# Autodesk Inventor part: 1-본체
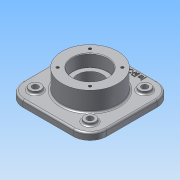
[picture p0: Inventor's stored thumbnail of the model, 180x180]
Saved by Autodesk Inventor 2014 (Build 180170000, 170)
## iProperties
Created: 2015-09
Part Number: 1-본체
Material: 알루미늄 6061
Document SubType Name: Modeling
Designer: study
Density: 2.71 g/cm^3
Appearance: 알루미늄 - 평지
Mass: 1464.68 g
Surface Area: 800.934 cm^2
Volume: 540.471 cm^3
Author: study
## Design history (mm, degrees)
sketch "스케치1"
  geometry: L1 (-75, -75)-(75, -75); L2 (75, -75)-(75, 75); L3 (75, 75)-(-75, 75); L4 (-75, 75)-(-75, -75); L5 (-75, -75)-(75, 75); L6 (75, -75)-(-75, 75); 1 further point
  constraints: 12 end point, 2 midpoint, 2 parallel, 2 perpendicular, 1 horizontal
  dimensions: "d0" = 150 distance of L2.end L3.end
extrude "돌출1" new body sketch "스케치1" distance "d1" = 12; taper "d2" = 0 deg
fillet "모깎기1" dims "d3" = 30
node "작업 평면1"
sketch "스케치2"
  geometry: C1 r 50 at (0, 0); 1 further point
  constraints: 1 centre point, 1 coincident
  dimensions: "d5" = 100 diameter of C1
extrude "돌출2" join sketch "스케치2" distance "d7" = 70; taper "d8" = 0 deg
sketch "스케치3"
  geometry: C1 r 50 at (0, 0) reference; C2 r 10 at (-49, 49); C3 r 10 at (49, 49); C4 r 10 at (-49, -49); C5 r 10 at (49, -49)
  constraints: 4 centre point, 3 equal radius, 2 horizontal alignment, 2 vertical alignment
  dimensions: "d45" = 20 diameter of C2; "d46" = 98 distance of C3.centre C2.centre; "d47" = 49 horizontal distance of C1.centre C2.centre; "d48" = 98 distance of C2.centre C4.centre; "d49" = 49 horizontal distance of C4.centre C1.centre
extrude "돌출3" join sketch "스케치3" distance "d10" = 5; taper "d11" = 0 deg
sketch "스케치7"
  geometry: C1 r 10 at (0, 0) reference; C2 r 10 at (98, 0) reference; C3 r 10 at (0, -98) reference; C4 r 10 at (98, -98) reference; 5 further points
  constraints: 4 coincident
hole "구멍4" sketch "스케치7" at (0, 0), (98, 0), (98, -98), (0, -98) diameter "d51" = 11; stored, may be unused: countersink angle "d55" = 90 deg, drill point angle "d57" = 0 deg; dims "d52" = 10, "d53" = 62, "d54" = 22, "d56" = 13
hole "구멍1" diameter "d18" = 45; stored, may be unused: countersink angle "d22" = 90 deg, drill point angle "d24" = 0 deg; dims "d16" = 10, "d17" = 10, "d19" = 6, "d20" = 62, "d21" = 22, "d23" = 80
hole "구멍2" diameter "d27" = 45; stored, may be unused: countersink angle "d31" = 90 deg, drill point angle "d33" = 0 deg; dims "d25" = 10, "d26" = 10, "d28" = 6, "d29" = 62, "d30" = 22, "d32" = 80
sketch "스케치5" dims "d34" = 82
  geometry: L1 (-28.991, -28.991)-(28.991, -28.991); L2 (28.991, -28.991)-(28.991, 28.991); L3 (28.991, 28.991)-(-28.991, 28.991); L4 (-28.991, 28.991)-(-28.991, -28.991); L5 (-28.991, -28.991)-(28.991, 28.991); L6 (28.991, -28.991)-(-28.991, 28.991); C1 r 50 at (0, 0) reference; 5 further points
  constraints: 12 end point, 5 coincident, 2 midpoint, 2 parallel, 2 perpendicular, 1 horizontal, 3 other
hole "구멍3" sketch "스케치5" at (-28.991, 28.991), (-28.991, -28.991), (28.991, -28.991), (28.991, 28.991) diameter "d35" = 4.917; stored, may be unused: countersink angle "d39" = 90 deg, drill point angle "d41" = 118 deg; dims "d36" = 10, "d37" = 62, "d38" = 22, "d40" = 13
node "작업 평면2"
sketch "스케치6"
  geometry: C1 r 50 at (0, 0) reference; 1 further point
  constraints: 1 vertical alignment, 1 other
  dimensions: "d42" = 65 distance of point (0, 65) C1.centre
feature "엠보싱1" sketch "스케치6" dims "d23" = 80, "d43" = 1, "d44" = 0
fillet "모깎기2" dims "d58" = 0.3
fillet "모깎기3" dims "d59" = 3
fillet "모깎기4" dims "d60" = 3
chamfer "모따기1" distance "d61" = 1; stored, may be unused: second distance "d62" = 2, angle "d63" = 45 deg
node "솔리드1"
mirror "대칭1"
other parameters: "d6" = 23
